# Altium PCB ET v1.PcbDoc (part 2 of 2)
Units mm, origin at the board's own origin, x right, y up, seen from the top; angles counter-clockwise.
Board outline 210 x 190 mm, 4 copper layers (Top Layer, GND, PWR, Bottom Layer), stack 0.538 mm thick; 137 components, 80 nets, 364 pads, 677 vias.
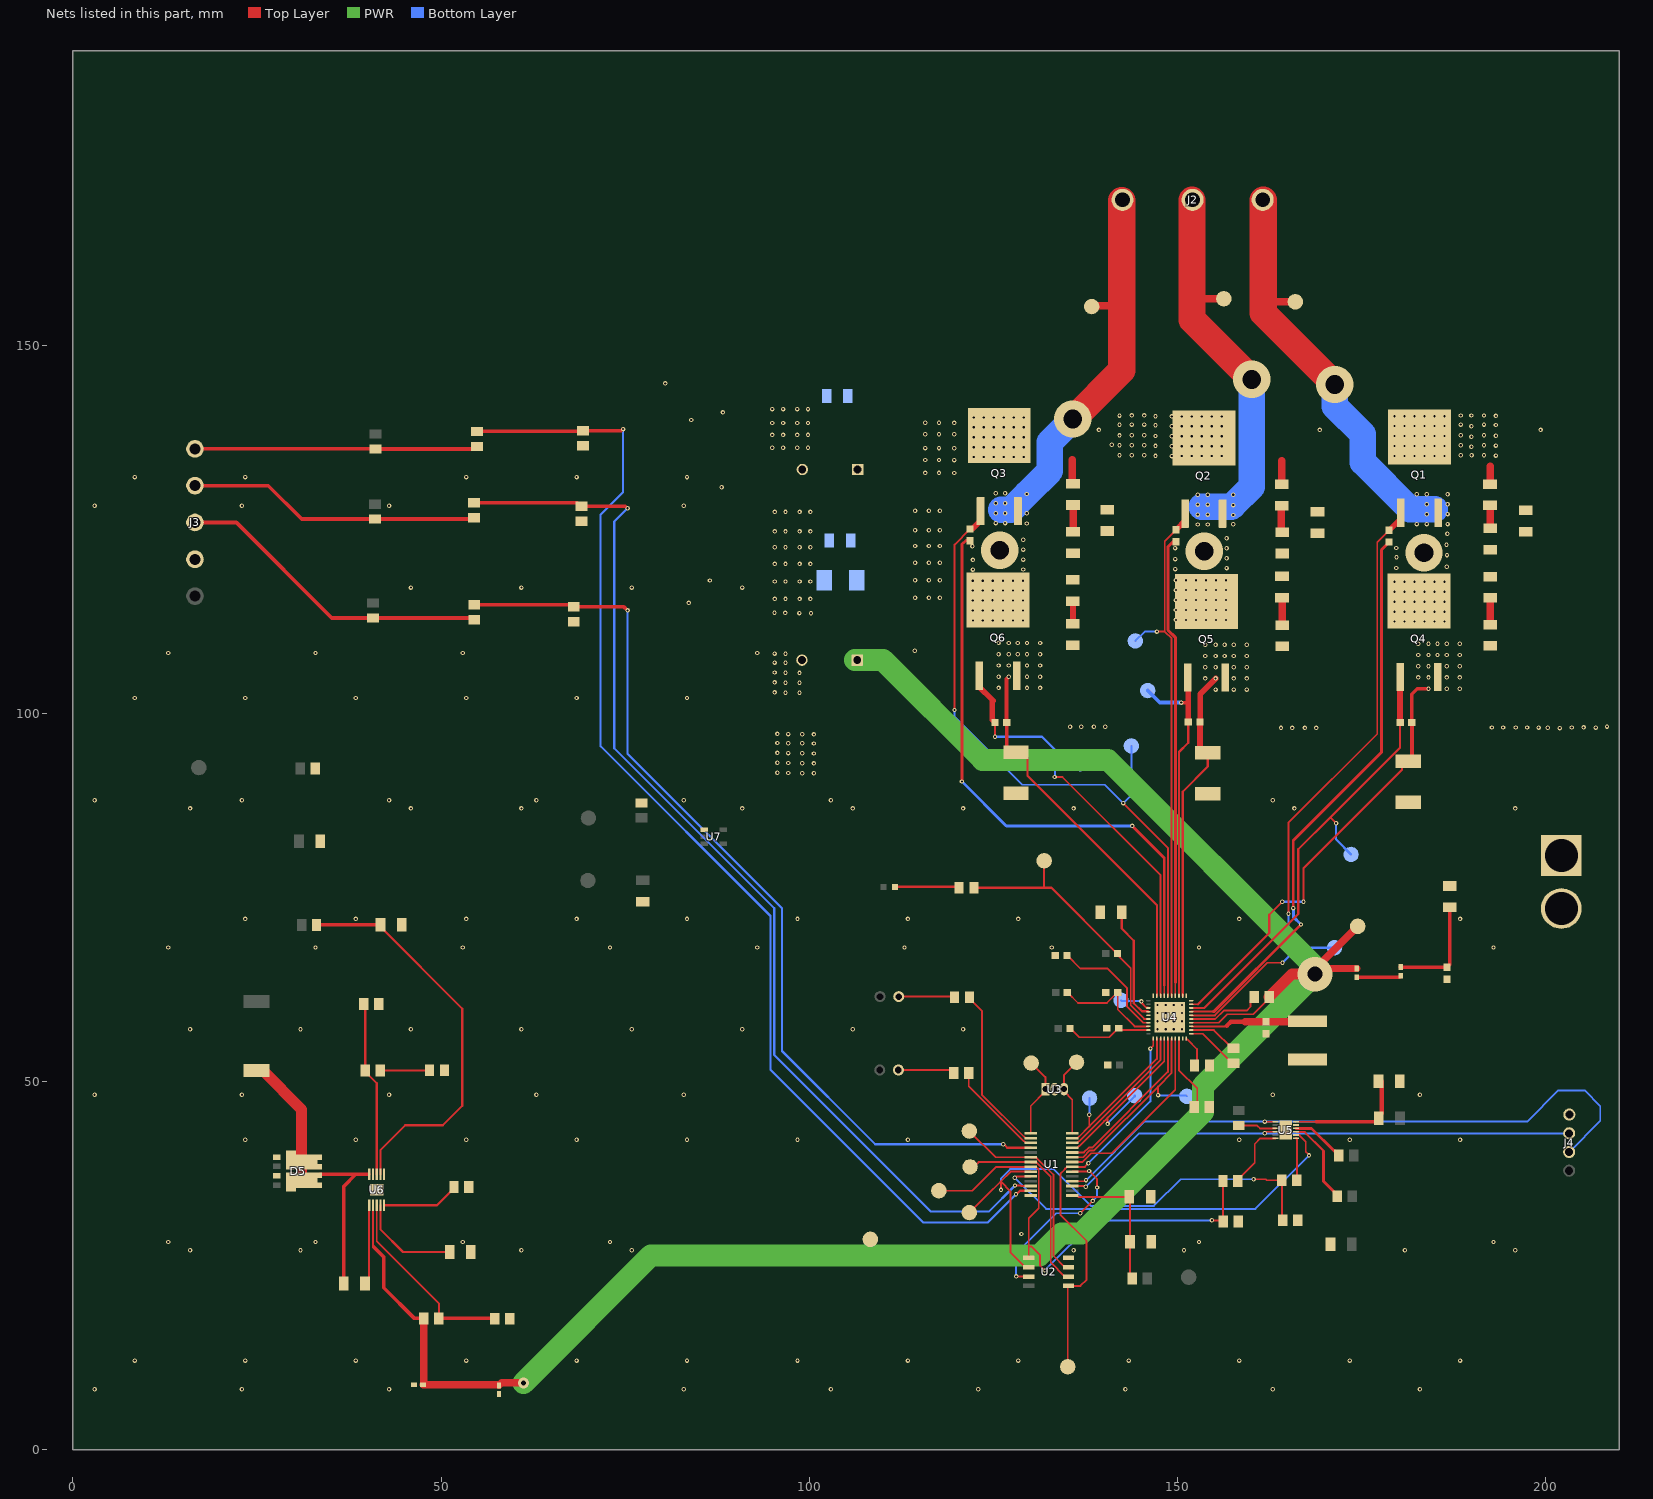
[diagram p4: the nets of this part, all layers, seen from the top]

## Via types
v1: diameter 0.6, hole 0.3, Top Layer to Bottom Layer, 669 vias
v2: diameter 5.08, hole 2.54, Top Layer to Bottom Layer, 6 vias
v3: diameter 1.5, hole 0.7, Top Layer to Bottom Layer, 1 vias
v4: diameter 4.7, hole 2, Top Layer to Bottom Layer, 1 vias

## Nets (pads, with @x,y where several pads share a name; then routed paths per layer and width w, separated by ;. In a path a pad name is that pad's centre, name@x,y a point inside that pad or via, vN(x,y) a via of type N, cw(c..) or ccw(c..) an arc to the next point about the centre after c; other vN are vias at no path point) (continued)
GND: C1.2 C2.2 C3.1 C4.2 C5.2 C6.1 C7.1 C9.1 C10.1 C12.1 C19.1 C20.1 C21.1 C28.1 C29.2 C30.1 C32.1 C33.2 C35.1 C36.1 C37.2 C38.2 C39.1 C41.1 C42.1 C43.1 C44.1 C45.1 C46.1 D3.1 D5.1 D5.3 J1.1 J3.4 J4.4 R6.1 R11.1 R12.1 R13.1 R14.1 R16.1 R18.2 R19.1 R23.1 R24.1 R25.1 R26.1 R37.1 R38.1 R39.1 R40.1 TP2.1 U1.28 U2.4 U3.2 U4.10 U4.11 U4.20 U4.25 U4.39 U4.41 U5.5 U5.13 U6.6 U6.9 U6.11 U7.1
  other v1: 2.949,8.222 22.949,8.222 42.949,8.222 82.949,8.222 102.949,8.222 122.949,8.222 142.949,8.222 162.949,8.222 182.949,8.222 8.407,12.116 23.407,12.116 38.407,12.116 53.407,12.116 68.407,12.116 83.407,12.116 98.407,12.116 113.407,12.116 128.407,12.116 143.407,12.116 158.407,12.116 173.407,12.116 188.407,12.116 15.907,27.116 30.907,27.116 60.907,27.116 75.907,27.116 135.907,27.116 150.907,27.116 180.907,27.116 195.907,27.116 12.949,28.222 32.949,28.222 52.949,28.222 72.949,28.222 152.949,28.222 192.949,28.222 128.829,29.317 23.407,42.116 38.407,42.116 53.407,42.116 68.407,42.116 83.407,42.116 98.407,42.116 113.407,42.116 158.407,42.116 173.407,42.116 188.407,42.116 2.949,48.222 22.949,48.222 42.949,48.222 62.949,48.222 82.949,48.222 162.949,48.222 182.949,48.222 15.907,57.116 30.907,57.116 45.907,57.116 60.907,57.116 75.907,57.116 90.907,57.116 105.907,57.116 120.907,57.116 147.325,57.113 148.425,57.113 149.525,57.113 150.625,57.113 147.325,58.213 148.425,58.213 149.525,58.213 150.625,58.213 147.325,59.313 148.425,59.313 149.525,59.313 150.625,59.313 147.325,60.413 148.425,60.413 149.525,60.413 150.625,60.413 12.949,68.222 32.949,68.222 52.949,68.222 72.949,68.222 92.949,68.222 112.949,68.222 132.949,68.222 152.949,68.222 192.949,68.222 23.407,72.116 38.407,72.116 53.407,72.116 68.407,72.116 83.407,72.116 98.407,72.116 113.407,72.116 128.407,72.116 158.407,72.116 188.407,72.116 15.907,87.116 45.907,87.116 60.907,87.116 90.907,87.116 105.907,87.116 120.907,87.116 135.907,87.116 165.907,87.116 195.907,87.116 2.949,88.222 22.949,88.222 42.949,88.222 62.949,88.222 82.949,88.222 102.949,88.222 162.949,88.222 100.64,91.887 99.063,91.905 97.156,91.925 95.683,91.954 100.64,93.234 97.156,93.283 99.063,93.263 95.683,93.313 100.64,94.579 97.156,94.63 99.063,94.61 95.683,94.659 100.64,95.929 97.156,95.975 99.063,95.955 95.683,96.004 100.64,97.171 99.063,97.188 97.156,97.208 95.683,97.237 201.932,98.025 164.088,98.058 165.612,98.058 167.33,98.058 168.863,98.058 200.321,98.074 192.731,98.106 194.255,98.106 195.973,98.106 197.506,98.106 199.068,98.09 203.576,98.106 206.83,98.09 205.187,98.123 135.432,98.204 136.956,98.204 138.674,98.204 140.207,98.204 208.36,98.237 8.407,102.116 23.407,102.116 38.407,102.116 53.407,102.116 68.407,102.116 83.407,102.116 98.687,102.819 96.78,102.839 95.307,102.868 98.687,104.177 96.78,104.197 95.307,104.226 98.687,105.523 96.78,105.543 95.307,105.573 96.78,106.889 95.307,106.918 96.78,108.122 95.307,108.151 12.949,108.222 32.949,108.222 52.949,108.222 92.949,108.222 100.242,113.618 98.666,113.648 96.759,113.668 95.286,113.697 83.64,115.024 95.313,115.575 96.783,115.575 98.69,115.575 100.16,115.575 45.907,117.116 60.907,117.116 75.907,117.116 90.907,117.116 95.313,117.937 96.783,117.937 98.69,117.937 100.16,117.937 86.511,118.073 95.313,120.325 96.783,120.325 98.69,120.325 100.16,120.325 95.313,122.591 96.783,122.591 98.69,122.591 100.16,122.591 95.313,124.737 96.783,124.737 98.69,124.737 100.16,124.737 95.313,127.386 96.783,127.386 98.69,127.386 100.16,127.386 2.949,128.222 22.949,128.222 42.949,128.222 82.949,128.222 88.107,130.729 8.407,132.116 23.407,132.116 53.407,132.116 68.407,132.116 83.407,132.116 94.991,136.092 96.461,136.092 98.368,136.092 99.838,136.092 94.991,137.845 96.461,137.845 98.368,137.845 99.838,137.845 94.991,139.464 96.461,139.464 98.368,139.464 99.838,139.464 83.994,139.875 88.284,140.903 94.991,141.356 96.461,141.356 98.368,141.356 99.838,141.356 80.449,144.838
IDRIVE: R10.1 R11.2 U4.28 | length 16
  Top Layer w0.254: R10.1@135.07,62.105 135.095,62.105 136.512,60.688 140.443,60.688 141.876,62.121 R11.2@141.901,62.121 ; R11.2@142.274,61.773 141.926,62.121 R11.2@141.901,62.121 ; U4.28@146.075,57.513 144.194,57.513 141.901,59.806 R11.2@141.901,62.121
MODE: R18.1 U4.27 | length 16.3
  Top Layer w0.254: R18.1@135.009,67.164 135.034,67.164 136.849,65.35 140.542,65.35 143.147,62.745 143.147,60.254 145.388,58.013 U4.27@146.075,58.013
MOTORA: C13.1 C16.1 C22.2 J2.1 Q1.3 Q4.2 TP17.1 U4.7 | length 136.3
  Top Layer w0.254: U4.7@151.875,59.513 154.882,59.513 ; v1@165.748,73.591 v1(165.757,73.582)
  Top Layer w0.4: 154.882,59.513 154.964,59.513 v1(166.799,71.349) ; v1@165.748,73.591 165.748,82.763 177.731,94.746 177.731,122.242 C13.1@178.798,123.309
  Top Layer w1: J2.1@161.593,169.78 J2.1@161.666,169.707 ; 161.666,154.401 163.194,155.929 TP17.1@166.022,155.929
  Top Layer w3.7: J2.1@161.666,169.707 161.666,154.401 v2(171.371,144.696)
  Bottom Layer w0.4: v1(165.757,73.582) 165.757,72.391 v1(166.799,71.349)
  Bottom Layer w3.6: v2(171.371,144.696) 171.371,141.761 175.196,137.936 175.196,134.152 181.599,127.749 184.939,127.749
  other v1: 179.504,112.49 180.864,112.49 182.224,112.49 183.584,112.49 184.944,112.49 186.304,112.49 179.504,113.84 180.864,113.84 182.224,113.84 183.584,113.84 184.944,113.84 186.304,113.84 179.504,115.19 180.864,115.19 182.224,115.19 183.584,115.19 184.944,115.19 186.304,115.19 179.504,116.54 180.864,116.54 182.224,116.54 183.584,116.54 184.944,116.54 186.304,116.54 179.504,117.89 180.864,117.89 182.224,117.89 183.584,117.89 184.944,117.89 186.304,117.89 179.749,119.766 186.607,119.944 179.774,121.239 186.632,121.519 179.749,122.484 186.556,122.941 186.683,124.414 182.529,125.731 183.889,125.731 186.708,125.736 183.889,127.081 186.708,127.086 183.889,128.431 186.708,128.436 182.529,129.781 183.889,129.781 186.708,129.786
  other v2: 183.508,121.823
MOTORB: C14.1 C17.1 C23.2 J2.2 Q2.3 Q5.2 TP18.1 U4.14 | length 117.4
  Top Layer w0.254: C14.1@149.433,123.345 C14.1@149.826,123.345 ; U4.14@149.725,61.663 149.725,63.459
  Top Layer w0.4: C14.1@149.433,123.345 148.748,122.661 148.748,111.33 149.725,110.353 149.725,63.459
  Top Layer w1: 152.008,156.362 152.029,156.34 TP18.1@156.312,156.34 ; J2.2@152.008,169.714 J2.2@152.073,169.78
  Top Layer w3.7: J2.2@152.008,169.714 152.008,156.362 152.008,153.499 v2(160.127,145.38)
  Bottom Layer w3.6: 153.309,128.064 157.352,128.064 v1(157.599,128.311) 160.127,130.839 v2(160.127,145.38)
  other v1: 149.803,112.717 151.163,112.717 152.523,112.717 153.883,112.717 155.243,112.717 156.603,112.717 149.803,114.067 151.163,114.067 152.523,114.067 153.883,114.067 155.243,114.067 156.603,114.067 149.803,115.417 151.163,115.417 152.523,115.417 153.883,115.417 155.243,115.417 156.603,115.417 149.803,116.767 151.163,116.767 152.523,116.767 153.883,116.767 155.243,116.767 156.603,116.767 149.803,118.117 151.163,118.117 152.523,118.117 153.883,118.117 155.243,118.117 156.603,118.117 149.732,119.625 156.692,119.752 149.732,120.975 156.692,121.102 149.695,122.469 156.692,122.452 156.692,123.802 152.767,125.678 154.127,125.678 157.599,125.72 157.599,126.965 152.767,127.028 154.127,127.028 152.767,128.378 154.127,128.378 152.767,129.728 154.127,129.728 157.599,129.733
  other v2: 153.67,122.037
MOTORC: C15.1 C18.1 C24.2 J2.3 Q3.3 Q6.2 TP19.1 U4.17 | length 138.2
  Top Layer w0.254: C15.1@121.375,123.52 C15.1@121.656,123.487 ; C15.1@121.476,123.487 C15.1@121.656,123.487 ; C15.1@121.836,123.487 C15.1@121.656,123.487 ; U4.17@148.225,61.663 148.225,63.102
  Top Layer w0.4: v1(120.749,90.767) 120.749,123.025 C15.1@121.375,123.52 ; v1(143.883,84.737) 148.225,80.395 148.225,63.102
  Top Layer w1: TP19.1@138.363,155.28 138.493,155.41 142.464,155.41 ; J2.3@142.464,169.69 J2.3@142.553,169.78
  Top Layer w3.7: v2@135.762,139.923 142.464,146.624 142.464,155.41 J2.3@142.464,169.69
  Bottom Layer w0.4: v1(120.749,90.767) 126.779,84.737 v1(143.883,84.737)
  Bottom Layer w3.6: 126.065,127.667 127.4,127.667 v1(129.557,129.824) 132.685,132.952 132.685,136.883 v2(135.812,140.01)
  other v1: 122.238,112.648 123.565,112.652 124.945,112.652 126.305,112.652 127.665,112.652 129.025,112.652 122.225,114.002 123.584,114.01 124.945,114.002 126.305,114.002 127.665,114.002 129.025,114.002 122.225,115.352 123.565,115.352 126.305,115.352 127.665,115.352 129.025,115.352 124.88,115.382 122.225,116.702 123.565,116.702 124.945,116.702 126.305,116.702 127.665,116.702 129.025,116.702 122.225,118.052 123.565,118.052 124.945,118.052 126.305,118.052 127.665,118.052 129.025,118.052 122.241,119.55 129.067,119.565 122.241,120.864 129.067,120.915 129.067,122.265 122.166,122.712 129.067,123.615 129.557,125.811 125.329,125.871 126.611,125.863 126.611,127.213 129.557,127.208 125.329,127.221 126.611,128.563 125.329,128.571 125.329,129.921 126.611,129.913
  other v2: 125.9,122.179
NetC1_1: C1.1 C2.1 R1.1 U1.1 | length 19.1
  Top Layer w0.254: U1.1@135.733,34.536 136.393,34.536 136.567,34.362 C2.1@143.492,34.362 143.57,34.284 C1.1@143.57,28.258 143.57,23.575 R1.1@143.874,23.271
NetC3_2: C3.2 R5.1 R6.2 | length 14.6
  Top Layer w0.5: R5.1@180.32,65.588 180.345,65.562 186.636,65.562 186.994,65.921 C3.2@186.994,73.679
NetC8_2: C8.2 U4.5 | length 10.3
  Top Layer w0.254: U4.5@151.875,58.513 155.157,58.513 156.306,59.662 159.416,59.662 159.941,60.187 159.941,61.009 C8.2@160.449,61.517
NetC9_2: C9.2 C10.2 J1.2 U4.3 | length 16.1
  Top Layer w0.254: U4.3@151.891,57.497 156.758,57.497 156.693,57.562 ; 159.244,58.094 159.244,58.119
  Top Layer w0.3: 156.644,57.513 156.693,57.562
  Top Layer w0.6: 156.693,57.562 157.25,58.119 159.244,58.119
  Top Layer w1: 159.244,58.119 162.042,58.119 C9.2@167.553,58.119
NetC11_1: C11.1 U4.1 | length 7.4
  Top Layer w0.254: U4.1@151.875,56.513 153.445,56.513 157.455,52.503 C11.1@157.62,52.503
NetC11_2: C11.2 U4.2 | length 6.8
  Top Layer w0.254: U4.2@151.875,57.013 154.977,57.013 157.455,54.535 C11.2@157.62,54.535
NetC12_2: C12.2 U4.38 | length 10.3
  Top Layer w0.254: U4.38@150.225,55.863 150.225,51.56 152.705,49.08 C12.2@152.705,46.577
NetC13_2: C13.2 Q1.1 TP13.1 U4.6 | length 89.9
  Top Layer w0.254: U4.6@151.875,59.013 155.106,59.013 162.239,66.147 v1(164.287,66.147) ; v1(165.099,72.799) 165.077,72.822 165.077,85.14 177.162,97.225 177.162,123.273 C13.2@178.798,124.909
  Top Layer w0.762: C13.2@178.798,124.909 180.295,126.406 Q1.1@180.295,127.417
  Bottom Layer w0.254: 165.099,67.32 v1(165.099,72.799)
  Bottom Layer w0.3: v1(164.287,66.147) 165.099,66.959 165.099,67.32 165.981,68.202 TP13.1@171.357,68.202
NetC14_2: C14.2 Q2.1 TP14.1 U4.15 | length 71.7
  Top Layer w0.254: v1(147.235,111.139) 148.291,111.138 ; U4.15@149.225,61.663 149.225,110.204 148.291,111.138 ; C14.2@149.826,124.945 148.291,123.41 148.291,111.138 ; Q2.1@150.934,127.18 Q2.1@150.966,127.147
  Top Layer w0.762: C14.2@149.826,124.945 151.147,126.266 Q2.1@151.147,127.253
  Bottom Layer w0.254: TP14.1@144.301,109.862 145.578,111.139 v1(147.235,111.139)
NetC15_2: C15.2 Q3.1 TP15.1 U4.16 | length 94.1
  Top Layer w0.254: v1(119.741,100.489) 119.741,122.94 C15.2@121.836,125.035 ; v1(142.669,87.836) 148.725,81.779 U4.16@148.725,61.663
  Top Layer w0.762: C15.2@121.836,125.087 122.153,125.087 123.241,126.175 Q3.1@123.241,127.394
  Bottom Layer w0.254: v1(119.741,100.489) 119.741,99.556 128.967,90.33 140.174,90.33 v1(142.669,87.836) 143.753,88.92 TP15.1@143.753,95.602
NetC16_2: C16.2 R7.1 | length 3.1
  Top Layer w1.016: C16.2@192.473,125.126 R7.1@192.473,128.254
NetC17_2: C17.2 R8.1 | length 3
  Top Layer w1.016: C17.2@164.139,124.581 164.139,127.562
NetC18_2: C18.2 R9.1 | length 3.1
  Top Layer w1.016: C18.2@135.851,124.944 R9.1@135.851,128.047
NetC22_1: C22.1 R12.2 | length 3.7
  Top Layer w1.016: C22.1@192.473,115.799 192.473,112.091 R12.2@192.482,112.082
NetC23_1: C23.1 R13.2 | length 3.5
  Top Layer w1.016: R13.2@164.254,112.032 C23.1@164.254,115.521
NetC24_1: C24.1 R14.2 | length 3.1
  Top Layer w0.762: R14.2@135.826,112.218 C24.1@135.826,115.276
NetC25_1: C25.1 Q4.3 R24.2 U4.9 | length 59.6
  Top Layer w0.254: U4.9@151.875,60.513 152.806,60.513
  Top Layer w0.3: 152.806,60.513 162.492,70.199 162.492,72.677 v1(164.256,74.441) ; v1(167.143,74.454) 167.143,78.984 180.498,92.338 180.498,92.763 181.248,93.513 R24.2@181.391,93.513
  Top Layer w0.508: R24.2@181.391,93.513 181.864,93.985 C25.1@181.864,98.809 ; C25.1@181.844,98.618 181.844,102.632 182.595,103.383 v1(184.118,103.383)
  Bottom Layer w0.3: v1(164.256,74.441) 164.269,74.454 v1(167.143,74.454)
  other v1: 186.581,103.383 188.359,103.383 182.721,104.907 184.118,104.907 186.581,104.907 188.359,104.907 182.721,106.431 184.118,106.431 186.581,106.431 188.359,106.431 182.721,107.955 184.118,107.955 185.337,107.955 186.581,107.955 188.359,107.955 184.118,109.479 185.337,109.479 186.581,109.479 188.359,109.479 182.721,109.491
NetC25_2: C25.2 Q4.1 TP21.1 U4.8 | length 64.1
  Top Layer w0.254: U4.8@151.875,60.013 153.671,60.013
  Top Layer w0.3: 153.671,60.013 166.438,72.78 166.438,81.577 170.823,85.961 ; v1(171.568,85.107) 170.823,85.852 170.823,85.961 ; C25.2@180.264,98.809 180.264,95.402 170.823,85.961
  Top Layer w0.762: C25.2@180.244,98.773 180.244,104.93 Q4.1@180.293,104.979
  Bottom Layer w0.3: v1(171.568,85.107) 171.568,82.888 TP21.1@173.596,80.861
NetC26_1: C26.1 Q5.1 TP22.1 U4.13 | length 50.1
  Top Layer w0.3: U4.13@150.225,61.663 150.225,94.772 151.487,96.034 C26.1@151.487,98.87
  Top Layer w0.5: v1(150.547,101.491) 150.566,101.472 151.419,101.472 151.49,101.401
  Top Layer w0.762: Q5.1@151.427,104.913 151.49,104.849 151.49,101.401 C26.1@151.49,98.848
  Bottom Layer w0.5: TP22.1@145.97,103.128 147.607,101.491 v1(150.547,101.491)
NetC26_2: C26.2 Q5.3 R25.2 U4.12 | length 44.9
  Top Layer w0.3: U4.12@150.725,61.663 150.725,89.386 154.143,92.804 R25.2@154.143,94.674
  Top Layer w0.762: R25.2@153.087,95.193 C26.2@153.087,98.87 ; C26.2@153.09,98.879 153.09,102.619 155.197,104.726 v1(155.197,104.774)
  other v1: 155.197,103.25 157.661,103.25 159.439,103.25 153.8,104.774 157.661,104.774 159.439,104.774 153.8,106.298 155.197,106.298 157.661,106.298 159.439,106.298 153.8,107.822 155.197,107.822 156.416,107.822 157.661,107.822 159.439,107.822 153.8,109.359 155.197,109.346 156.416,109.346 157.661,109.346 159.439,109.346
NetC27_1: C27.1 Q6.3 R26.2 U4.19 | length 52.9
  Top Layer w0.203: Q6.3@128.197,105.065 Q6.3@128.21,105.052
  Top Layer w0.3: R26.2@128.087,94.739 128.912,94.739 129.662,93.989 129.662,91.547 147.225,73.985 U4.19@147.225,61.663
  Top Layer w0.508: C27.1@126.801,98.726 126.801,104.691 v1(127.119,105.009) ; C27.1@126.833,98.801 126.833,95.385 127.479,94.739 R26.2@128.087,94.739
  other v1: 125.722,103.485 129.583,103.485 131.361,103.485 125.722,105.009 129.583,105.009 131.361,105.009 125.722,106.533 127.119,106.533 129.583,106.533 131.361,106.533 125.722,108.057 127.119,108.057 128.338,108.057 129.583,108.057 131.361,108.057 127.119,109.581 128.338,109.581 129.583,109.581 131.361,109.581 125.722,109.593
NetC27_2: C27.2 Q6.1 TP23.1 U4.18 | length 62.1
  Top Layer w0.254: 124.885,101.77 125.049,101.605 ; 125.201,101.667 125.201,101.757 ; v1(133.338,91.382) 134.403,91.382 147.725,78.06 U4.18@147.725,61.663
  Top Layer w0.3: v1(125.233,96.852) C27.2@125.233,98.801
  Top Layer w0.762: Q6.1@123.026,103.693 123.026,103.691 124.96,101.757 ; Q6.1@123.117,103.693 Q6.1@123.117,105.052 ; 124.885,101.77 124.885,99.149 125.114,98.92 125.114,98.895 125.208,98.801 C27.2@125.233,98.801
  Bottom Layer w0.3: v1(125.233,96.852) 131.622,96.852 133.376,95.097 133.376,92.409 ; v1(133.338,91.382) 133.376,91.421 133.376,92.409 ; TP23.1@136.801,93.195 134.162,93.195 133.376,92.409
NetC28_2: C28.2 U4.40 | length 4.4
  Top Layer w0.254: U4.40@151.225,55.863 151.225,55.707 151.242,55.69 151.398,55.69 152.673,54.415 152.673,52.286 C28.2@152.748,52.211
NetC30_2: C30.2 R20.2 TP7.1 U1.23 U2.6 | length 74.6
  Top Layer w0.254: TP7.1@121.75,32.222 124.16,34.632 124.192,34.632 126.002,36.443 ; v1(126.056,35.306) 126.056,36.389 ; U2.6@129.818,24.799 129.343,24.799 127.339,26.803 127.339,35.106 126.056,36.389 ; U1.23@130.094,37.786 127.345,37.786 126.002,36.443 ; v1(160.367,36.756) 162.01,36.756 162.16,36.606 R20.2@164.206,36.606 164.206,31.267 C30.2@164.306,31.167 ; 126.002,36.443 126.056,36.389
  Bottom Layer w0.254: v1(126.056,35.306) 126.056,36.893 127.297,38.134 133.232,38.134 138.239,33.127 146.818,33.127 150.447,36.756 v1(160.367,36.756)
NetC31_2: C31.2 U5.4 | length 7.4
  Top Layer w0.4: U5.4@166.13,43.656 168.228,43.656 171.316,40.568 171.481,40.568 171.916,40.133 C31.2@171.916,39.968
NetC33_1: C33.1 R31.2 U1.18 | length 128.9
  Top Layer w0.3: v1(126.371,41.493) 126.452,41.493 126.909,41.036 U1.18@130.094,41.036
  Top Layer w0.5: R31.2@54.515,114.786 67.546,114.786 67.843,114.489 C33.1@68.008,114.489 74.832,114.489 75.304,114.017 v1(75.332,114.017)
  Bottom Layer w0.3: v1(75.332,114.017) 75.332,94.531 96.295,73.568 96.295,54.162 108.964,41.493 v1(126.371,41.493)
NetC34_2: C34.2 U5.3 | length 11.6
  Top Layer w0.3: U5.3@166.287,43.147 167.325,43.147 169.859,40.614
  Top Layer w0.4: 169.859,40.614 169.859,36.47 171.726,34.603 C34.2@171.726,34.438
NetC35_2: C35.2 R21.2 TP8.1 U1.22 U2.5 | length 64.6
  Top Layer w0.254: TP8.1@117.618,35.192 119.409,35.192 ; 119.397,35.179 119.409,35.192 ; U2.5@129.818,26.069 129.818,27.628 ; v1(132.014,24.359) 131.372,25.001 131.372,26.434 130.177,27.628 129.818,27.628 ; v1(154.704,31.168) 156.068,31.168 C35.2@156.222,31.014 156.222,36.5 R21.2@156.198,36.523 ; 119.409,35.192 122.154,35.192 125.398,38.436 U1.22@130.094,38.436 130.755,38.436 130.973,38.217 131.038,38.217 131.186,38.069 131.186,32.84 129.818,31.471 129.818,27.737 129.818,27.628
  Bottom Layer w0.254: v1(132.014,24.359) 138.823,31.168 v1(154.704,31.168)
NetC36_2: C36.2 U4.24 | length 15.5
  Top Layer w0.3: C36.2@142.449,73.005 142.449,70.8 144.087,69.162 144.087,60.662 145.196,59.553 146.035,59.553 U4.24@146.075,59.513
NetC37_1: C37.1 R32.2 U1.26 | length 150.3
  Top Layer w0.3: v1(127.958,35.903) 128.732,35.903 128.799,35.836 U1.26@130.094,35.836
  Top Layer w0.5: R32.2@54.473,128.619 68.477,128.619 68.922,128.174 C37.1@69.087,128.174 75.023,128.174 75.304,127.892 v1(75.332,127.892)
  Bottom Layer w0.3: v1(75.332,127.892) 73.536,126.097 73.536,112.705 73.536,95.278 95.26,73.555 95.26,53.626 116.534,32.352 124.408,32.352 v1(127.958,35.903)
NetC38_1: C38.1 R33.2 U1.27 | length 163.5
  Top Layer w0.3: v1(128.087,34.718) 128.168,34.718 128.636,35.186 U1.27@130.094,35.186
  Top Layer w0.5: R33.2@54.884,138.302 54.938,138.355 69.217,138.355 C38.1@69.271,138.409 74.482,138.409 74.704,138.632 v1(74.731,138.632)
  Bottom Layer w0.3: v1(74.731,138.632) 74.731,130.097 71.671,127.037 71.671,95.573 94.733,72.511 94.733,51.629 115.474,30.888 124.258,30.888 v1(128.087,34.718)
NetC40_1: C40.1 U6.1 | length 10.8
  Top Layer w0.254: C40.1@39.67,22.591 39.67,22.866 40.235,23.431 U6.1@40.235,33.194
NetC40_2: C40.2 D5.5 D5.6 D5.7 D5.8 L1.1 U6.10 | length 40.2
  Top Layer w0.5: D5.7@33.487,37.283 33.487,37.333 33.572,37.417 38.412,37.417 ; C40.2@36.77,22.591 36.77,35.775 38.412,37.417 ; U6.10@40.156,37.417 38.412,37.417
  Top Layer w1.5: L1.1@24.917,51.498 25.806,51.498 31.052,46.251 D5.5@31.052,39.1 D5.7@31.052,36.62
NetC44_2: C44.2 U6.4 | length 13.9
  Top Layer w0.3: U6.4@41.758,33.217 41.758,29.954 44.843,26.869 C44.2@51.159,26.869
NetC45_2: C45.2 R36.2 U6.8 | length 23.9
  Top Layer w0.3: C45.2@39.503,60.565 39.706,60.363 R36.2@39.706,51.521 39.706,51.356 41.258,49.803 U6.8@41.258,37.417
NetC46_2: C46.2 R36.1 | length 6.7
  Top Layer w0.3: R36.1@41.738,51.521 48.409,51.521 C46.2@48.435,51.547
NetC47_1: C47.1 U5.9 | length 5.2
  Top Layer w0.254: C47.1@158.332,44.046 160.842,44.046 161.232,43.656 U5.9@163.336,43.656
NetD1_2: D1.2 R2.2 | length 7.7
  Top Layer w0.3: D1.2@112.121,51.585 119.253,51.585 R2.2@119.641,51.198
NetD2_2: D2.2 R3.2 | length 7.6
  Top Layer w0.3: D2.2@112.162,61.556 119.65,61.556 R3.2@119.738,61.468
NetD4_2: D4.2 R27.1 | length 8.7
  Top Layer w0.254: R27.1@120.234,76.463 R27.1@120.348,76.349
  Top Layer w0.3: D4.2@111.671,76.463 R27.1@120.234,76.463
NetJ3_1: J3.1 R29.1 R33.1 | length 38.5
  Top Layer w0.5: J3.1@16.571,135.953 16.577,135.948 41.081,135.948 R29.1@41.086,135.942 54.392,135.942 54.719,136.27 R33.1@54.884,136.27
NetJ3_2: J3.2 R28.1 R32.1 | length 39.8
  Top Layer w0.5: J3.2@16.571,130.953 26.542,130.953 31.076,126.42 R28.1@41.022,126.42 54.14,126.42 54.308,126.587 R32.1@54.473,126.587
NetJ3_3: J3.3 R30.1 R31.1 | length 43.4
  Top Layer w0.5: J3.3@16.571,125.953 22.203,125.953 35.167,112.989 R30.1@40.774,112.989 54.116,112.989 54.35,112.754 R31.1@54.515,112.754
NetJ4_2: J4.2 U1.4 U5.7 | length 87.2
  Top Layer w0.254: U1.4@135.733,36.486 137.435,36.486 137.59,36.641 v1(137.603,36.641) ; v1(161.874,44.581) 161.886,44.581 161.912,44.556 U5.7@163.336,44.556
  Bottom Layer w0.254: v1(137.603,36.641) 145.543,44.581 v1(161.874,44.581) 197.507,44.581 201.743,48.817 205.322,48.817 207.448,46.691 207.448,44.675 J4.2@203.221,40.448
NetJ4_3: J4.3 U1.3 U5.10 | length 72.1
  Top Layer w0.254: U1.3@135.733,35.836 137.456,35.836 137.561,35.73 v1(137.574,35.73) ; v1(161.866,42.984) 161.878,42.984 162.1,43.206 U5.10@163.336,43.206
  Bottom Layer w0.254: v1(137.574,35.73) 144.786,42.943 161.547,42.943 161.622,43.018 161.647,42.993 161.857,42.993 v1(161.866,42.984) 161.868,42.986 203.219,42.986 J4.3@203.221,42.988
NetR2_1: R2.1 U1.17 | length 13.4
  Top Layer w0.254: R2.1@121.673,51.198 121.673,49.382 129.151,41.904 129.216,41.904 129.434,41.686 U1.17@130.094,41.686
NetR3_1: R3.1 U1.16 | length 23
  Top Layer w0.254: R3.1@121.77,61.468 121.77,61.303 123.461,59.611 123.461,48.243 129.151,42.554 129.216,42.554 129.434,42.336 U1.16@130.094,42.336
NetR4_1: R4.1 R5.2 | length 6.1
  Top Layer w0.5: R4.1@174.381,64.179 180.211,64.179 180.32,64.288 R5.2@180.32,64.388
NetR17_2: R17.2 R27.2 TP26.1 U4.26 | length 38
  Top Layer w0.254: R17.2@141.682,67.391 141.782,67.391 141.955,67.218 141.955,67.118 143.668,65.405 143.668,60.354 145.494,58.528 146.06,58.528 U4.26@146.075,58.513
  Top Layer w0.3: R27.2@122.38,76.349 131.888,76.349 ; TP26.1@131.914,80.007 131.888,79.981 131.888,78.364 131.888,76.349 ; R17.2@141.882,67.391 141.857,67.391 132.899,76.349 131.888,76.349
NetR20_1: R20.1 U5.1 | length 5.8
  Top Layer w0.3: U5.1@166.13,42.306 166.202,42.306 166.238,42.27 R20.1@166.238,36.606
NetR21_1: R21.1 U5.12 | length 9.1
  Top Layer w0.254: R21.1@158.23,36.523 158.23,36.688 160.514,38.972 160.514,41.537 161.283,42.306 U5.12@163.336,42.306
NetR22_2: R22.2 R23.2 U5.6 | length 16.7
  Top Layer w0.254: U5.6@166.13,44.556 168.886,44.556
  Top Layer w0.5: 168.886,44.556 176.945,44.556 177.345,44.956 R22.2@177.345,45.039
  Top Layer w0.6: R22.2@177.345,45.039 177.345,45.314 177.76,45.728 R23.2@177.76,50.074
NetR34_1: R34.1 R37.2 U6.7 | length 54.8
  Top Layer w0.3: U6.7@41.758,37.417 41.758,40.698 45.141,44.081 50.239,44.081 52.884,46.725 52.884,59.92 41.775,71.028 R37.2@41.775,71.303
  Top Layer w0.5: R34.1@33.089,71.297 41.758,71.297 41.769,71.297 R37.2@41.775,71.303
NetR35_1: R35.1 R38.2 U6.3 | length 26.6
  Top Layer w0.254: U6.3@41.258,33.217 41.258,28.346 49.696,19.907 R35.1@49.696,17.852
  Top Layer w0.5: R35.1@49.696,17.852 56.985,17.852 R38.2@57.322,17.516
NetR39_2: R39.2 U6.5 | length 10.6
  Top Layer w0.3: U6.5@42.258,33.217 49.443,33.217 51.751,35.526 R39.2@51.751,35.691
NetTP3_1: TP3.1 U1.15 U3.1 | length 11.2
  Top Layer w0.254: U1.15@130.094,42.986 130.094,46.697 132.073,48.676 U3.1@132.073,48.991 132.073,50.614 TP3.1@130.156,52.531
NetTP4_1: TP4.1 U1.14 U3.3 | length 10.8
  Top Layer w0.254: U1.14@135.733,42.985 135.733,47.555 134.613,48.676 U3.3@134.613,48.991 134.613,50.945 TP4.1@136.311,52.643
NetTP5_1: TP5.1 U1.21 U2.2 | length 26.9
  Top Layer w0.254: TP5.1@121.849,38.424 122.348,38.424 123.01,39.086 U1.21@130.094,39.086 130.145,39.035 130.87,39.035 132.804,37.101 132.804,25.469 134.743,23.529 U2.2@135.218,23.529
NetTP6_1: TP6.1 U1.20 U2.3 | length 27.6
  Top Layer w0.254: TP6.1@121.757,43.299 125.321,39.736 U1.20@130.094,39.736 130.145,39.685 130.87,39.685 133.185,37.37 133.185,26.358 134.743,24.799 U2.3@135.218,24.799
NetTP16_1: TP16.1 U1.7 U2.1 U4.31 | length 54.8
  Top Layer w0.254: TP16.1@135.118,11.28 135.118,22.16 U2.1@135.218,22.259 136.836,22.259 137.68,23.103 137.68,28.36 134.11,31.931 134.11,37.473 134.641,38.004 134.641,38.069 134.79,38.217 134.854,38.217 135.073,38.436 U1.7@135.733,38.436 ; U1.7@135.682,38.385 U1.7@135.733,38.436 ; v1(137.928,38.91) 137.453,38.436 U1.7@135.733,38.436 ; v1(146.348,54.49) 146.725,54.866 U4.31@146.725,55.863
  Bottom Layer w0.254: v1(137.928,38.91) 146.348,47.33 v1(146.348,54.49)
NetTP20_1: TP20.1 U1.13 U4.32 | length 22.6
  Top Layer w0.254: U1.13@135.733,42.336 136.393,42.336 136.612,42.554 136.676,42.554 138.053,43.931 ; v1(138.039,45.52) 138.039,43.946 138.053,43.931 ; U4.32@147.225,55.863 147.225,53.102 138.053,43.931
  Bottom Layer w0.254: v1(138.039,45.52) 138.061,45.543 138.061,47.746 TP20.1@138.083,47.769
NetTP24_1: TP24.1 U1.11 U4.34 | length 26.7
  Top Layer w0.254: U1.11@135.733,41.036 136.393,41.036 136.612,41.254 136.676,41.254 140.062,44.639 ; 140.066,44.639 140.062,44.639 ; v1@140.443,44.261 v1(140.537,44.261) 140.537,45.114 ; U4.34@148.225,55.863 148.225,52.802 140.537,45.114 ; 140.062,44.639 140.537,45.114
  Bottom Layer w0.3: v1(140.537,44.261) 140.537,44.337 144.218,48.018 TP24.1@144.218,48.095
NetTP25_1: TP25.1 U1.9 U4.36 | length 28.1
  Top Layer w0.254: U1.9@135.733,39.736 137.194,39.736 138.123,40.664 138.711,40.664 147.391,49.344 ; v1(147.391,48.175) 147.391,49.344 ; U4.36@149.225,55.863 149.233,55.855 149.233,51.186 147.391,49.344
  Bottom Layer w0.254: v1(147.391,48.175) 147.457,48.109 151.206,48.109 TP25.1@151.3,48.015
NetTP27_1: TP27.1 U4.23 | length 4.2
  Top Layer w0.3: v1(145.118,60.909) 145.175,60.852 145.175,60.675 145.798,60.053 146.035,60.053 U4.23@146.075,60.013
  Bottom Layer w0.3: TP27.1@142.359,61.044 142.437,60.966 145.061,60.966 v1(145.118,60.909)
NetU1_6: U1.6 U2.7 | length 25.3
  Top Layer w0.254: v1(128.11,23.546) 128.118,23.538 129.81,23.538 U2.7@129.818,23.529 ; U1.6@135.733,37.786 137.921,37.786 138.004,37.868 v1(138.017,37.868) 139.101,36.784 v1(139.101,35.623) ; v1(136.827,32.136) 136.828,32.136 v1(138.501,33.808) v1(138.501,33.808)
  Bottom Layer w0.254: v1(128.11,23.546) 128.11,26.718 133.528,32.136 v1(136.827,32.136) ; v1(138.501,33.808) 139.101,34.407 v1(139.101,35.623)
NetU1_8: U1.8 U4.37 | length 25
  Top Layer w0.254: U1.8@135.733,39.085 137.083,39.085 138.28,40.283 141.121,40.283 149.725,48.887 U4.37@149.725,55.863
NetU1_10: U1.10 U4.35 | length 22.1
  Top Layer w0.254: U1.10@135.733,40.385 137.305,40.385 137.965,41.045 138.439,41.045 148.725,51.331 U4.35@148.725,55.863
NetU1_12: U1.12 U4.33 | length 19.6
  Top Layer w0.254: U1.12@135.733,41.685 136.393,41.685 136.612,41.904 136.676,41.904 147.725,52.952 U4.33@147.725,55.863
NetU1_24: U1.24 U5.2 | length 50.7
  Top Layer w0.254: v1(127.916,36.966) 127.929,36.966 128.098,37.136 U1.24@130.094,37.136 ; U5.2@166.13,42.756 166.143,42.743 166.573,42.743 167.446,41.869 167.446,40.507 167.89,40.064 v1(167.89,39.988)
  Bottom Layer w0.254: v1(127.916,36.966) 132.168,32.714 160.616,32.714 v1(167.89,39.988)
VDC: C4.1 C5.1 C6.2 C7.2 C8.1 C19.2 C20.2 C21.2 C42.2 C43.2 D3.2 Q1.2 Q2.2 Q3.2 R4.2 R7.2 R8.2 R9.2 R35.2 TP9.1 U4.4 U6.2 | length 297
  Top Layer w0.254: U6.2@40.75,33.209 40.75,27.669 40.866,27.553 ; U4.4@151.883,58.005 155.623,58.005 156.772,59.154 160.283,59.154 162.481,61.351 C8.1@162.481,61.517
  Top Layer w0.5: 40.866,27.553 42.229,26.19 42.229,22.018 46.395,17.852 R35.2@47.664,17.852
  Top Layer w1: R35.2@47.664,17.852 47.664,8.939 C43.2@47.546,8.82 57.807,8.82 C42.2@57.87,8.757 58.204,9.092 v3(61.206,9.092) ; v4(168.7,64.617) v4@169.462,65.379 ; R4.2@174.381,65.379 v4@169.462,65.379 ; TP9.1@174.503,71.105 169.462,66.063 v4@169.462,65.379
  Top Layer w1.016: R9.2@135.75,131.385 135.75,134.494 ; R8.2@164.19,131.352 164.19,134.349 ; R7.2@192.53,131.324 192.53,133.62
  Top Layer w1.5: C8.1@162.481,61.517 165.582,64.617 v4(168.7,64.617)
  PWR w1.5: v4(168.7,64.617) v4@168.7,65.563
  PWR w3: v3(61.206,9.092) 78.492,26.378 131.25,26.378 134.274,29.402 137.001,29.402 153.481,45.883 153.481,49.398 v4(168.7,64.617) ; C4.1@106.232,107.265 110.012,107.265 123.564,93.713 140.551,93.713 v4@168.7,65.563
  other v1: 114.343,108.521 114.387,115.74 116.262,115.74 117.756,115.74 114.387,118.102 116.262,118.102 117.756,118.102 114.387,120.489 116.262,120.489 117.756,120.489 114.387,122.755 116.262,122.755 117.756,122.755 114.387,124.902 116.262,124.902 117.756,124.902 114.387,127.551 116.262,127.551 117.756,127.551 119.697,132.669 115.759,132.681 117.633,132.681 119.697,134.422 115.759,134.434 117.633,134.434 122.352,134.831 123.712,134.831 125.072,134.831 126.432,134.831 127.792,134.831 129.152,134.831 149.244,134.965 150.604,134.965 151.964,134.965 153.324,134.965 154.684,134.965 156.044,134.965 179.491,134.991 180.851,134.991 182.211,134.991 183.571,134.991 184.931,134.991 186.291,134.991 147.039,134.996 193.276,135.038 142.152,135.076 188.505,135.089 189.97,135.078 191.651,135.089 143.813,135.098 145.515,135.098 115.759,136.053 117.633,136.053 119.697,136.04 122.352,136.181 123.712,136.181 125.072,136.181 126.432,136.181 127.792,136.181 129.152,136.181 189.937,136.239 149.244,136.315 150.604,136.315 151.964,136.315 153.324,136.315 154.684,136.315 156.044,136.315 147.039,136.355 179.491,136.341 180.851,136.341 182.211,136.341 183.571,136.341 184.931,136.341 186.291,136.341 193.276,136.397 142.152,136.435 143.813,136.456 145.515,136.456 188.505,136.448 191.651,136.448 141.105,136.505 122.352,137.531 123.712,137.531 125.072,137.531 126.432,137.531 127.792,137.531 129.152,137.531 189.937,137.585 149.244,137.665 150.604,137.665 151.964,137.665 153.324,137.665 154.684,137.665 156.044,137.665 147.039,137.701 179.491,137.691 180.851,137.691 182.211,137.691 183.571,137.691 184.931,137.691 186.291,137.691 193.276,137.743 142.152,137.781 143.813,137.803 145.515,137.803 188.505,137.794 191.651,137.794 119.697,137.932 115.759,137.945 117.633,137.945 139.343,138.521 169.343,138.521 199.343,138.521 122.352,138.881 123.712,138.881 125.072,138.881 126.432,138.881 127.792,138.881 129.152,138.881 149.244,139.015 150.604,139.015 151.964,139.015 153.324,139.015 154.684,139.015 156.044,139.015 179.491,139.041 180.851,139.041 182.211,139.041 183.571,139.041 184.931,139.041 186.291,139.041 189.937,139.033 147.039,139.149 193.276,139.191 142.152,139.229 143.813,139.25 145.515,139.25 188.505,139.242 191.651,139.242 119.697,139.482 115.759,139.494 117.633,139.494 122.352,140.231 123.712,140.231 125.072,140.231 126.432,140.231 127.792,140.231 129.152,140.231 149.244,140.365 150.604,140.365 151.964,140.365 153.324,140.365 154.684,140.365 156.044,140.365 147.039,140.389 179.491,140.391 180.851,140.391 182.211,140.391 183.571,140.391 184.931,140.391 186.291,140.391 193.276,140.431 142.152,140.469 189.937,140.478 143.813,140.49 145.515,140.49 188.505,140.482 191.651,140.482
VDS: R15.1 R16.2 U4.29 | length 11.8
  Top Layer w0.254: R15.1@135.423,57.229 135.448,57.229 136.649,56.027 140.769,56.027 141.999,57.258 R16.2@142.024,57.258 142.269,57.013 U4.29@146.075,57.013
pads on no net: D5.2 D5.4 U1.2 U1.5 U1.19 U1.25 U4.21 U4.22 U5.8 U5.11 U7.4 U7.5

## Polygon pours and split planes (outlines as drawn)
GND on Top Layer "GND-GND" (solid, pour order 44): 0.001,98.869 210.028,98.869 210.029,0 0.001,0
GND on Top Layer "Top Layer-GND" (solid, pour order 32): 104.327,101.356 104.327,109.74 101.33,112.738 101.33,149.479 0.001,149.479 0.001,101.356
VDC on Top Layer "Top Layer-VM" (solid, remove dead copper, pour order 31): 118.995,101.456 118.995,130.589 120.605,132.199 210.029,132.199 210.029,149.394 105.016,149.394 105.016,101.457
NetC9_2 on Top Layer "NONET_L-01_P-001" (solid, pour order 29): 197.838,76.422 ccw(c197.838,442.182) 207.242,76.543 cw(c207.253,76.13) 207.666,76.13 207.666,55.926 cw(c206.537,55.926) 205.842,55.037 165.323,55.037 cw(c165.323,55.48) 164.881,55.511 165.195,59.959 cw(c165.462,59.94) 165.45,60.207 191.025,61.36 ccw(c190.929,63.493) 192.975,62.885 196.756,75.614 cw(c197.838,75.293)
GND on Top Layer "GND_L01_P036" (solid, remove dead copper, pour order 36): 195.939,125.339 210.039,125.339 210.051,97.486 191.091,97.486 191.091,112.861 191.814,113.584 193.668,113.584 195.939,115.855
VDC on Top Layer "Top Layer-SHB" (solid, pour order 39): 198.068,127.122 198.22,127.274 198.22,132.38 198.093,132.507 196.518,132.507 196.398,132.386 196.398,127.276 196.552,127.122
GND on Top Layer "GND_L01_P040" (solid, remove dead copper, pour order 40): 167.793,125.217 172.292,125.217 172.304,97.393 162.945,97.393 162.945,112.739 163.668,113.462 165.522,113.462 167.793,115.732
VDC on Top Layer "Top Layer-SHB" (solid, pour order 41): 169.922,127 170.075,127.152 170.075,132.258 169.948,132.385 168.373,132.385 168.252,132.264 168.252,127.154 168.406,127
GND on Top Layer "GND_L01_P042" (solid, remove dead copper, pour order 42): 139.231,125.382 144.087,125.382 144.099,97.472 134.383,97.472 134.383,112.903 135.106,113.627 136.96,113.627 139.231,115.897
VDC on Top Layer "Top Layer-SHB" (solid, pour order 43): 141.36,127.165 141.513,127.317 141.513,132.422 141.386,132.549 139.811,132.549 139.69,132.429 139.69,127.319 139.844,127.165
MOTORA on Top Layer "Top_NetC13_1" (solid, pour order 30): 178.798,111.346 187.16,111.346 187.537,111.723 187.537,117.539 193.658,117.539 193.658,123.076 187.537,123.076 187.537,130.395 187.205,130.726 182.378,130.726 181.806,130.155 181.832,130.129 181.832,125.202 180.536,123.906 178.593,123.906 178.326,123.64 178.326,111.702
NetC25_1 on Top Layer "Top Layer-SLA" (solid, pour order 33): 181.832,109.962 182.111,110.241 189.992,110.241 189.992,102.773 182.01,102.773 181.832,102.952
NetC26_2 on Top Layer "Top Layer-SLA" (solid, pour order 34): 153.146,109.968 162.013,109.968 162.013,102.602 153.146,102.602
NetC27_1 on Top Layer "Top Layer-SLA" (solid, pour order 35): 124.693,110.282 133.272,110.282 133.272,102.916 125.413,102.916 124.693,103.637
MOTORC on Top Layer "Top Layer-NetC15_1" (solid, pour order 37): 121.571,111.422 129.932,111.422 130.31,111.8 130.31,117.283 137.135,117.283 137.135,122.791 130.31,122.791 130.31,130.471 129.978,130.802 125.151,130.802 124.579,130.231 124.604,130.205 124.604,125.278 123.385,124.059 121.442,124.059 121.15,123.767 121.15,111.74
MOTORB on Top Layer "Top Layer-NetC14_1" (solid, remove dead copper, pour order 38): 149.815,111.28 158.177,111.28 158.554,111.658 158.554,117.7 165.306,117.699 165.306,122.66 158.554,122.66 158.554,130.329 158.173,130.711 153.445,130.711 152.577,130.056 152.577,125.115 151.554,123.84 149.61,123.84 149.344,123.574 149.344,111.636
GND on Bottom Layer "GND-GND" (solid, pour order 89): 0.001,98.767 210.029,98.766 210.03,0 0.001,0
GND on Bottom Layer "Top Layer-GND" (solid, pour order 83): 103.678,100.878 103.678,114.913 103.069,149.394 0.001,149.394 0.001,100.878
no net on Bottom Layer "Bottom Layer-SHB" (solid, pour order 86): 137.025,110.93 137.025,130.539 121.987,130.539 120.92,129.472 120.92,111.616 121.606,110.93
VDC on Bottom Layer "Top Layer-VDC" (solid, remove dead copper, pour order 84): 118.874,101.321 118.874,130.192 120.484,131.802 210.029,131.802 210.028,149.394 104.895,149.394 104.895,101.321
no net on Bottom Layer "Bottom Layer-SHB" (solid, pour order 87): 194.077,111.031 194.077,130.64 179.04,130.64 177.973,129.573 177.973,111.717 178.658,111.031
GND on Bottom Layer "Bottom Layer-GND" (solid, pour order 90): 94.055,102.081 94.813,102.839 94.813,102.887 102.078,102.887 102.914,102.052 102.914,96.129 102.458,95.674 94.711,95.674 94.055,96.33
no net on Bottom Layer "Bottom Layer-SLA" (solid, pour order 92): 195.331,101.327 195.331,110.145 177.002,110.145 177.002,101.327
no net on Bottom Layer "Bottom Layer-SLA" (solid, pour order 91): 166.632,100.83 166.632,109.648 148.304,109.648 148.303,100.83
no net on Bottom Layer "Bottom Layer-SLA" (solid, pour order 88): 138.316,101.055 138.316,109.872 119.988,109.872 119.988,101.055
no net on Bottom Layer "Bottom Layer-SHB" (solid, pour order 85): 165.4,111.191 165.4,130.8 150.363,130.8 149.296,129.733 149.296,111.877 149.981,111.191
GND on GND "GND-GND" (solid, pour order 59): 0,98.882 210.029,98.882 210.03,0 0,0
GND on GND "Top Layer-GND" (solid, pour order 53): 103.723,101.242 104.275,101.604 104.275,109.801 103.131,110.945 103.131,149.394 0,149.394 0,101.242
VDC on GND "Top Layer-VM" (solid, remove dead copper, pour order 54): 108.701,101.251 118.887,101.251 118.887,130.556 120.497,132.166 210.029,132.166 210.029,149.394 104.909,149.394 104.909,101.251
GND on GND "Bottom Layer-GND" (solid, pour order 60): 94.068,102.444 94.826,103.202 94.826,103.251 102.091,103.251 102.927,102.415 102.927,96.492 102.472,96.037 94.725,96.037 94.068,96.694
NetC25_1 on GND "Bottom Layer-SLA" (solid, pour order 82): 195.306,101.682 195.306,110.5 176.977,110.5 176.977,101.682
NetC26_2 on GND "Bottom Layer-SLA" (solid, pour order 81): 166.572,101.166 166.572,109.984 148.243,109.984 148.243,101.166
NetC27_1 on GND "Bottom Layer-SLA" (solid, pour order 80): 138.365,101.466 138.365,110.284 120.037,110.284 120.037,101.466
MOTORB on GND "Bottom Layer-SHB" (solid, pour order 55): 165.413,111.554 165.413,131.164 150.376,131.164 149.309,130.096 149.309,112.24 149.995,111.554
MOTORC on GND "Bottom Layer-SHB" (solid, pour order 56): 137.038,111.294 137.038,130.903 122.001,130.903 120.934,129.836 120.934,111.979 121.62,111.294
MOTORA on GND "Bottom Layer-SHB" (solid, pour order 57): 194.09,111.395 194.09,131.004 179.053,131.004 177.986,129.937 177.986,112.08 178.672,111.395
GND on PWR "GND-GND" (solid, pour order 76): 0,98.882 210.029,98.882 210.03,0 0,0
GND on PWR "Top Layer-GND" (solid, pour order 70): 103.692,101.242 103.692,110.75 103.008,149.394 0,149.394 0,101.242
no net on PWR "Bottom Layer-SHB" (solid, pour order 73): 137.038,111.294 137.038,130.903 122.001,130.903 120.934,129.836 120.934,111.979 121.62,111.294
no net on PWR "Bottom Layer-SHB" (solid, pour order 74): 194.09,111.395 194.09,131.004 179.053,131.004 177.986,129.937 177.986,112.08 178.672,111.395
VDC on PWR "Top Layer-VM" (solid, remove dead copper, pour order 71): 118.887,101.251 118.887,130.556 120.497,132.166 210.029,132.166 210.028,149.394 104.909,149.394 104.909,101.251
GND on PWR "Bottom Layer-GND" (solid, pour order 77): 94.068,102.444 94.826,103.202 94.826,103.251 102.091,103.251 102.927,102.415 102.927,96.492 102.472,96.037 94.725,96.037 94.068,96.694
NetC26_2 on PWR "Bottom Layer-SLA" (solid, pour order 78): 166.645,101.193 166.645,110.011 148.317,110.011 148.317,101.193
NetC25_1 on PWR "Bottom Layer-SLA" (solid, pour order 79): 195.344,101.69 195.344,110.508 177.015,110.508 177.015,101.69
no net on PWR "Bottom Layer-SLA" (solid, pour order 75): 138.33,101.418 138.33,110.236 120.001,110.236 120.001,101.418
no net on PWR "Bottom Layer-SHB" (solid, pour order 72): 165.413,111.554 165.413,131.164 150.376,131.164 149.309,130.096 149.309,112.24 149.995,111.554

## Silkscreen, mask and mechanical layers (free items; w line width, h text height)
Mechanical 1:
  the board outline again, w0.254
